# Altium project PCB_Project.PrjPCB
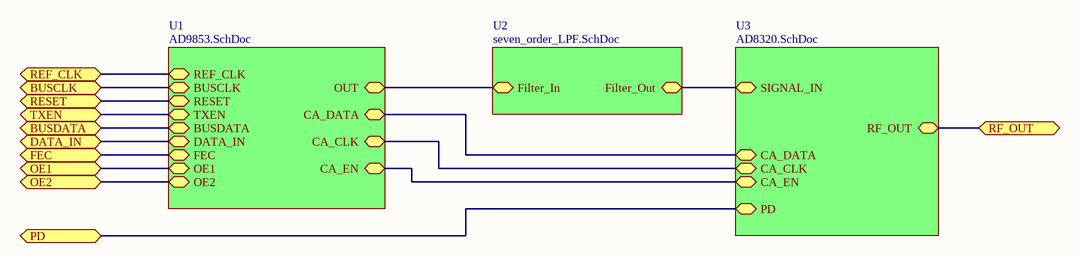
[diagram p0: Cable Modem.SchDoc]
4 sheets, 37 parts. Net scope: hierarchical (ports join the sheet entries above them; power ports are global).
Sheets:
  Cable Modem.SchDoc
    U1 = AD9853.SchDoc
    U2 = seven_order_LPF.SchDoc
    U3 = AD8320.SchDoc

## Sheet Cable Modem.SchDoc
size B

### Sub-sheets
U1 = AD9853.SchDoc: REF_CLK, BUSCLK, RESET, TXEN, BUSDATA, OE1, OE2, DATA_IN, FEC, OUT, CA_DATA, CA_CLK, CA_EN
U2 = seven_order_LPF.SchDoc: Filter_Out, Filter_In
U3 = AD8320.SchDoc: SIGNAL_IN, CA_DATA, CA_EN, CA_CLK, PD, RF_OUT

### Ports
BUSCLK, BUSDATA, DATA_IN, FEC, OE1, OE2, PD, REF_CLK, RESET, RF_OUT, TXEN

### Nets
NetC1_1: port RF_OUT, sheet U3/RF_OUT
NetC21_1: sheet U1/OUT, sheet U2/Filter_In
NetC26_2: sheet U2/Filter_Out, sheet U3/SIGNAL_IN
NetU1_1: sheet U1/CA_DATA, sheet U3/CA_DATA
NetU1_2: sheet U1/CA_CLK, sheet U3/CA_CLK
NetU1_3: sheet U1/CA_EN, sheet U3/CA_EN
NetU1_6: port PD, sheet U3/PD
NetU2_1: port OE1, sheet U1/OE1
NetU2_2: port FEC, sheet U1/FEC
NetU2_4: port BUSCLK, sheet U1/BUSCLK
NetU2_6: port RESET, sheet U1/RESET
NetU2_8: port TXEN, sheet U1/TXEN
NetU2_11: port BUSDATA, sheet U1/BUSDATA
NetU2_19: port OE2, sheet U1/OE2
NetU3_38: port REF_CLK, sheet U1/REF_CLK
NetU3_41: port DATA_IN, sheet U1/DATA_IN

## Sheet AD9853.SchDoc
size B
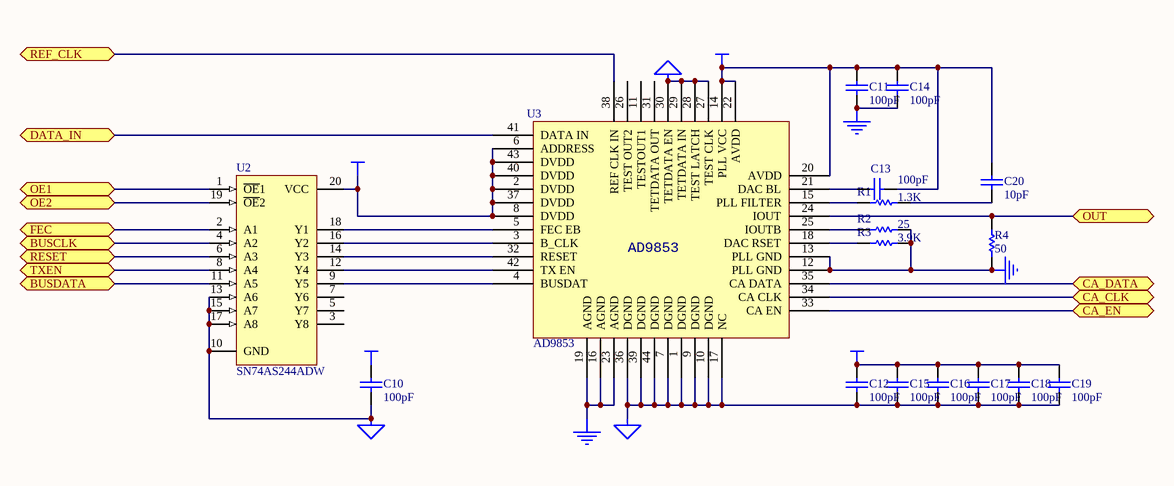
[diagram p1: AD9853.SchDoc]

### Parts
C10  100pF  [RAD-0.3]
C11  100pF  [RAD-0.3]
C12  100pF  [RAD-0.3]
C13  100pF  [RAD-0.3]
C14  100pF  [RAD-0.3]
C15  100pF  [RAD-0.3]
C16  100pF  [RAD-0.3]
C17  100pF  [RAD-0.3]
C18  100pF  [RAD-0.3]
C19  100pF  [RAD-0.3]
C20  10pF  [RAD-0.3]
R1  1.3K  [AXIAL-0.3]
R2  25  [AXIAL-0.3]
R3  3.9K  [AXIAL-0.3]
R4  50  [AXIAL-0.3]
U2  SN74AS244ADW  [SO-G20/G7.1]
U3  AD9853

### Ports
BUSCLK, BUSDATA, CA_CLK, CA_DATA, CA_EN, DATA_IN, FEC, OE1, OE2, OUT, REF_CLK, RESET, TXEN

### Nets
+5V: C11.2 C13.2 C14.2 C20.1 U3.14(PLL_VCC) U3.20(AVDD) U3.22(AVDD)
AGND: U3.16(AGND) U3.19(AGND) U3.23(AGND)
DUT +V: C10.2 C12.2 C15.2 C16.2 C17.2 C18.2 C19.2 U2.20(VCC) U3.2(DVDD) U3.6(ADDRESS) U3.8(DVDD) U3.37(DVDD) U3.40(DVDD) U3.43(DVDD)
GND: C11.1 C14.1 R2.2 R3.2 R4.1 U3.12(PLL_GND) U3.13(PLL_GND)
SGND: C10.1 C12.1 C15.1 C16.1 C17.1 C18.1 C19.1 U2.10(GND) U2.13(A6) U2.15(A7) U2.17(A8) U3.1(DGND) U3.7(DGND) U3.9(DGND) U3.10(DGND) U3.17(NC) U3.27(TEST_CLK) U3.28(TEST_LATCH) U3.29(TETDATA_IN) U3.30(TETDATA_EN) U3.36(DGND) U3.39(DGND) U3.44(DGND)
NetC13_1: C13.1 U3.21(DAC_BL)
NetC20_2: C20.2 R1.2
NetC21_1: R4.2 U3.24(IOUT) ; port OUT
NetR1_1: R1.1 U3.15(PLL_FILTER)
NetR2_1: R2.1 U3.25(IOUTB)
NetR3_1: R3.1 U3.18(DAC_RSET)
NetU1_1: U3.35(CA_DATA) ; port CA_DATA
NetU1_2: U3.34(CA_CLK) ; port CA_CLK
NetU1_3: U3.33(CA_EN) ; port CA_EN
NetU2_1: U2.1(~{OE}1) ; port OE1
NetU2_2: U2.2(A1) ; port FEC
NetU2_4: U2.4(A2) ; port BUSCLK
NetU2_6: U2.6(A3) ; port RESET
NetU2_8: U2.8(A4) ; port TXEN
NetU2_9: U2.9(Y5) U3.4(BUSDAT)
NetU2_11: U2.11(A5) ; port BUSDATA
NetU2_12: U2.12(Y4) U3.42(TX_EN)
NetU2_14: U2.14(Y3) U3.32(RESET)
NetU2_16: U2.16(Y2) U3.3(B_CLK)
NetU2_18: U2.18(Y1) U3.5(FEC_EB)
NetU2_19: U2.19(~{OE}2) ; port OE2
NetU3_38: U3.38(REF_CLK_IN) ; port REF_CLK
NetU3_41: U3.41(DATA_IN) ; port DATA_IN

Not connected (* = marked no-connect by the designer): U2 3(Y8) 5(Y7) 7(Y6); U3 11(TESTOUT1) 26(TEST_OUT2) 31(TETDATA_OUT)

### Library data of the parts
C10-C20 = Cap: Capacitor; Manufacturer: Generic Components; Class I: Passive
R1-R4 = Res1: Resistor; Manufacturer: Generic Components; Class I: Passive
U2 = SN74AS244ADW: Octal Buffer/Driver with 3-State Outputs; Manufacturer: Texas Instruments; Package Information: Latest Revision: Dec-1998; Class I: Logic; Class II: Buffer/Line Driver
U3 = AD9853: Programmable Digital QPSK/16-QAM Modulator

## Sheet seven_order_LPF.SchDoc
size B
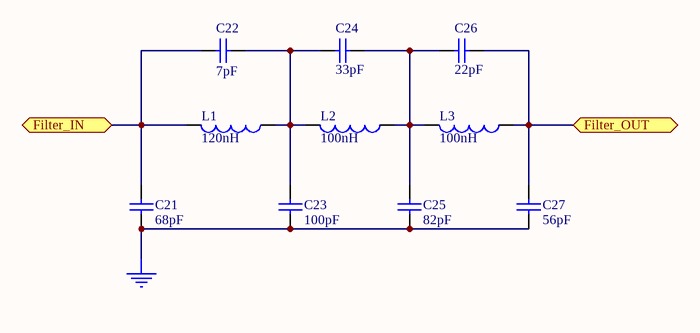
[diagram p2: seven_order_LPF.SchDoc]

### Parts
C21  68pF  [C3216-1206]
C22  7pF  [C3216-1206]
C23  100pF  [C3216-1206]
C24  33pF  [C3216-1206]
C25  82pF  [C3216-1206]
C26  22pF  [C3216-1206]
C27  56pF  [C3216-1206]
L1  120nH  [C1005-0402]
L2  100nH  [C1005-0402]
L3  100nH  [C1005-0402]

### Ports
Filter_IN, Filter_OUT

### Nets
GND: C21.2 C23.2 C25.2 C27.2
NetC21_1: C21.1 C22.1 L1.2 ; port Filter_IN
NetC22_2: C22.2 C23.1 C24.1 L1.1 L2.2
NetC24_2: C24.2 C25.1 C26.1 L2.1 L3.2
NetC26_2: C26.2 C27.1 L3.1 ; port Filter_OUT

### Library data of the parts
C21-C27 = Cap Semi: Capacitor (Semiconductor SIM Model); Manufacturer: Generic Components; Class I: Passive
L1-L3 = Inductor: Manufacturer: Generic Components; Class I: Passive

## Sheet AD8320.SchDoc
size B
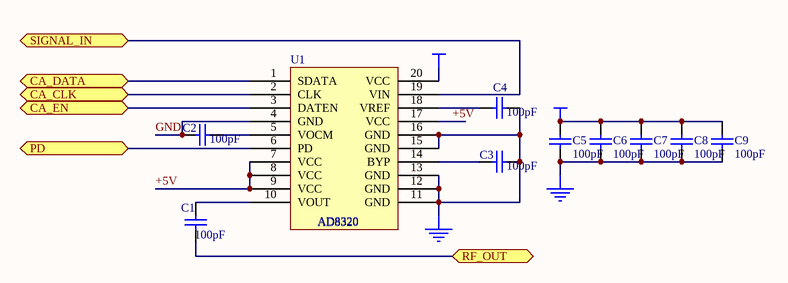
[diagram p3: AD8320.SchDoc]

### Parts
C1  100pF  [RAD-0.3]
C2  100pF  [RAD-0.3]
C3  100pF  [RAD-0.3]
C4  100pF  [RAD-0.3]
C5  100pF  [RAD-0.3]
C6  100pF  [RAD-0.3]
C7  100pF  [RAD-0.3]
C8  100pF  [RAD-0.3]
C9  100pF  [RAD-0.3]
U1  AD8320

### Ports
CA_CLK, CA_DATA, CA_EN, PD, RF_OUT, SIGNAL_IN

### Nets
+5V: C5.2 C6.2 C7.2 C8.2 C9.2 U1.7(VCC) U1.8(VCC) U1.9(VCC) U1.17(VCC) U1.20(VCC)
GND: C2.1 C3.2 C4.1 C5.1 C6.1 C7.1 C8.1 C9.1 U1.4(GND) U1.11(GND) U1.12(GND) U1.13(GND) U1.15(GND) U1.16(GND)
NetC1_1: C1.1 ; port RF_OUT
NetC1_2: C1.2 U1.10(VOUT)
NetC2_2: C2.2 U1.5(VOCM)
NetC3_1: C3.1 U1.14(BYP)
NetC4_2: C4.2 U1.18(VREF)
NetC26_2: U1.19(VIN) ; port SIGNAL_IN
NetU1_1: U1.1(SDATA) ; port CA_DATA
NetU1_2: U1.2(CLK) ; port CA_CLK
NetU1_3: U1.3(DATEN) ; port CA_EN
NetU1_6: U1.6(PD) ; port PD

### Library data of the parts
C1-C9 = Cap: as C10 on sheet AD9853

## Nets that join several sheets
+5V: AD9853 (7 pins), AD8320 (10 pins)
GND: AD9853 (7 pins), seven_order_LPF (C21.2 C23.2 C25.2 C27.2), AD8320 (14 pins)
NetC21_1: AD9853 (R4.2 U3.24), seven_order_LPF (C21.1 C22.1 L1.2)
NetC26_2: seven_order_LPF (C26.2 C27.1 L3.1), AD8320 (U1.19)
NetU1_1: AD9853 (U3.35), AD8320 (U1.1)
NetU1_2: AD9853 (U3.34), AD8320 (U1.2)
NetU1_3: AD9853 (U3.33), AD8320 (U1.3)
